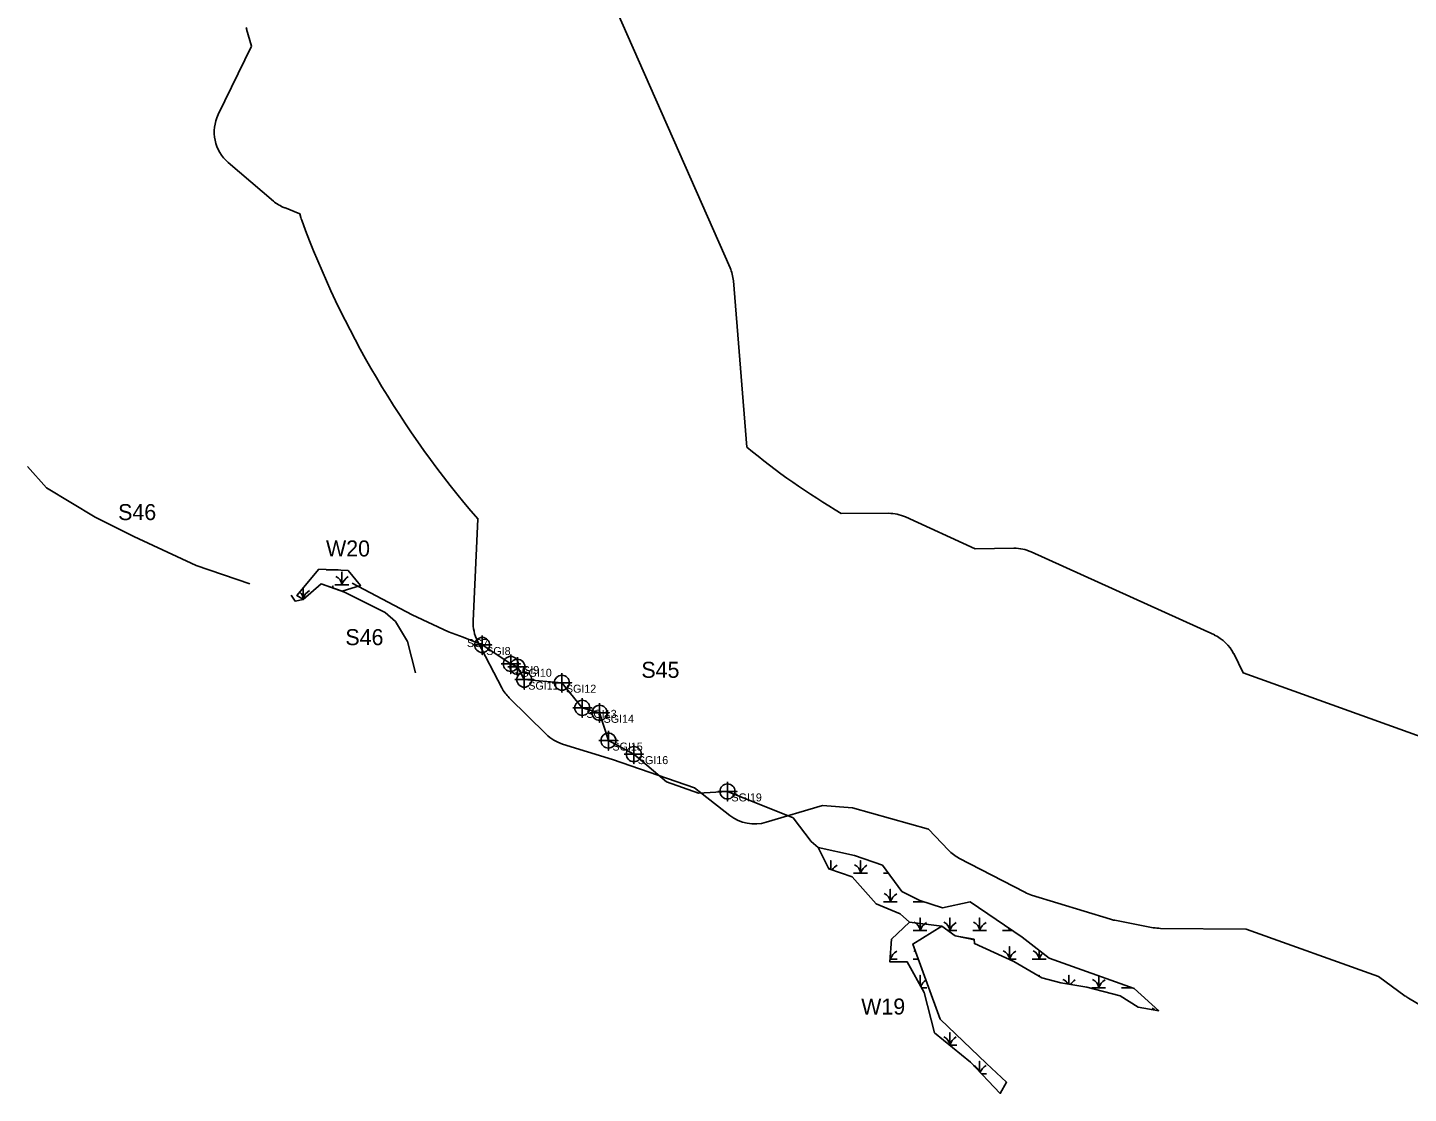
# Model space of a CAD drawing. Extents: x 1253697 to 1278588, y 912189 to 981699.
# Drawn here: x 1261409 to 1263135, y 937677 to 939009 of the extents above; entities that cross this region are included whole.
import ezdxf

# ---------------------------------------------------------------- set-up
doc = ezdxf.new("R2010")
doc.units = 0
for name, color, linetype in [('Default', 7, 'Continuous'), ('Exist Environmental Wetland Boundary', 7, 'Continuous'), ('Exist Hydro Jurisdictional Stream or Body of Water Mitigable', 7, 'Continuous'), ('Exist Hydro Jurisdictional Stream or Body of Water Mitigable Cogo Comment', 7, 'Continuous'), ('Exist Hydro Jurisdictional Stream or Body of Water Mitigable Cogo Number', 7, 'Continuous'), ('Exist Hydro Jurisdictional Stream or Body of Water Mitigable Cogo Point CELL', 7, 'Continuous'), ('Exist Hydro Swamp or Marsh', 7, 'Continuous')]:
    doc.layers.add(name, color=color, linetype=linetype)

msp = doc.modelspace()

# ---------------------------------------------------------------- linework, layer by layer
at = {"layer": 'Default'}
for p, q in [((1262287, 938708.6), (1262120.5, 939086.2)), ((1262287, 938708.6), (1262120.5, 939086.2)), ((1262287, 938708.6), (1262120.5, 939086.2)), ((1262287, 938708.6), (1262120.5, 939086.2)), ((1261659.9, 938840), (1261716.3, 938792)), ((1261659.9, 938840), (1261716.3, 938792)), ((1261659.9, 938840), (1261716.3, 938792)), ((1261659.9, 938840), (1261716.3, 938792)), ((1262307.8, 938484.5), (1262291.1, 938692.4)), ((1262307.8, 938484.5), (1262291.1, 938692.4)), ((1262307.8, 938484.5), (1262291.1, 938692.4)), ((1262307.8, 938484.5), (1262291.1, 938692.4)), ((1262485.1, 938401.9), (1262425.9, 938401.8)), ((1262485.1, 938401.9), (1262425.9, 938401.8)), ((1262485.1, 938401.9), (1262425.9, 938401.8)), ((1262485.1, 938401.9), (1262425.9, 938401.8)), ((1261971.9, 938394.7), (1261965.8, 938267.6)), ((1261971.9, 938394.7), (1261965.8, 938267.6)), ((1261971.9, 938394.7), (1261965.8, 938267.6)), ((1261971.9, 938394.7), (1261965.8, 938267.6)), ((1262892.2, 938249.9), (1262663.1, 938353.8)), ((1262892.2, 938249.9), (1262663.1, 938353.8)), ((1262892.2, 938249.9), (1262663.1, 938353.8)), ((1262892.2, 938249.9), (1262663.1, 938353.8)), ((1261971.4, 938242.1), (1262001.7, 938184)), ((1261971.4, 938242.1), (1262001.7, 938184)), ((1261971.4, 938242.1), (1262001.7, 938184)), ((1261971.4, 938242.1), (1262001.7, 938184)), ((1262010.9, 938171.5), (1262057, 938125.9)), ((1262010.9, 938171.5), (1262057, 938125.9)), ((1262010.9, 938171.5), (1262057, 938125.9)), ((1262010.9, 938171.5), (1262057, 938125.9)), ((1262572.9, 937971.3), (1262655.5, 937928.5)), ((1262572.9, 937971.3), (1262655.5, 937928.5)), ((1262572.9, 937971.3), (1262655.5, 937928.5)), ((1262572.9, 937971.3), (1262655.5, 937928.5)), ((1262663.8, 937925.1), (1262762.3, 937894.9)), ((1262663.8, 937925.1), (1262762.3, 937894.9)), ((1262663.8, 937925.1), (1262762.3, 937894.9)), ((1262663.8, 937925.1), (1262762.3, 937894.9)), ((1262767.6, 937893.5), (1262815.9, 937884.3)), ((1262767.6, 937893.5), (1262815.9, 937884.3)), ((1262767.6, 937893.5), (1262815.9, 937884.3)), ((1262767.6, 937893.5), (1262815.9, 937884.3)), ((1263134.6, 937796.3), (1263224.7, 937742.8)), ((1263134.6, 937796.3), (1263224.7, 937742.8)), ((1263134.6, 937796.3), (1263224.7, 937742.8)), ((1263134.6, 937796.3), (1263224.7, 937742.8))]:
    msp.add_line(p, q, dxfattribs=at)
for points in [[(1261682.8, 939006.8), (1261688.9, 938985.4), (1261647.3, 938900)], [(1261682.8, 939006.8), (1261688.9, 938985.4), (1261647.3, 938900)], [(1261682.8, 939006.8), (1261688.9, 938985.4), (1261647.3, 938900)], [(1261682.8, 939006.8), (1261688.9, 938985.4), (1261647.3, 938900)], [(1261730, 938783.7), (1261749.3, 938775.9), (1261750.5, 938771.4)], [(1261730, 938783.7), (1261749.3, 938775.9), (1261750.5, 938771.4)], [(1261730, 938783.7), (1261749.3, 938775.9), (1261750.5, 938771.4)], [(1261730, 938783.7), (1261749.3, 938775.9), (1261750.5, 938771.4)], [(1262641.7, 938358.2), (1262593.1, 938357.5), (1262506.1, 938397.4)], [(1262641.7, 938358.2), (1262593.1, 938357.5), (1262506.1, 938397.4)], [(1262641.7, 938358.2), (1262593.1, 938357.5), (1262506.1, 938397.4)], [(1262641.7, 938358.2), (1262593.1, 938357.5), (1262506.1, 938397.4)], [(1263346.7, 938104.1), (1263218.8, 938098.3), (1262928.3, 938202.5), (1262916.3, 938226.6)], [(1263346.7, 938104.1), (1263218.8, 938098.3), (1262928.3, 938202.5), (1262916.3, 938226.6)], [(1263346.7, 938104.1), (1263218.8, 938098.3), (1262928.3, 938202.5), (1262916.3, 938226.6)], [(1263346.7, 938104.1), (1263218.8, 938098.3), (1262928.3, 938202.5), (1262916.3, 938226.6)], [(1262077.5, 938113.7), (1262140, 938094.5), (1262242.5, 938059.1), (1262286.8, 938024.4)], [(1262077.5, 938113.7), (1262140, 938094.5), (1262242.5, 938059.1), (1262286.8, 938024.4)], [(1262077.5, 938113.7), (1262140, 938094.5), (1262242.5, 938059.1), (1262286.8, 938024.4)], [(1262077.5, 938113.7), (1262140, 938094.5), (1262242.5, 938059.1), (1262286.8, 938024.4)], [(1262332.1, 938015.9), (1262402.3, 938037.1), (1262440, 938033.9), (1262534.8, 938007.3), (1262559.8, 937981.2)], [(1262332.1, 938015.9), (1262402.3, 938037.1), (1262440, 938033.9), (1262534.8, 938007.3), (1262559.8, 937981.2)], [(1262332.1, 938015.9), (1262402.3, 938037.1), (1262440, 938033.9), (1262534.8, 938007.3), (1262559.8, 937981.2)], [(1262332.1, 938015.9), (1262402.3, 938037.1), (1262440, 938033.9), (1262534.8, 938007.3), (1262559.8, 937981.2)], [(1262824.8, 937883.4), (1262932, 937882.5), (1263097.2, 937823.2), (1263130.8, 937798.8)], [(1262824.8, 937883.4), (1262932, 937882.5), (1263097.2, 937823.2), (1263130.8, 937798.8)], [(1262824.8, 937883.4), (1262932, 937882.5), (1263097.2, 937823.2), (1263130.8, 937798.8)], [(1262824.8, 937883.4), (1262932, 937882.5), (1263097.2, 937823.2), (1263130.8, 937798.8)]]:
    msp.add_lwpolyline(points, dxfattribs=at)
for centre, radius, start, end in [((1261730.9, 939020.6), 50, 193.9029, 196.0582), ((1261730.9, 939020.6), 50, 193.9029, 196.0582), ((1261730.9, 939020.6), 50, 193.9029, 196.0582), ((1261730.9, 939020.6), 50, 193.9029, 196.0582), ((1261692.3, 938878.1), 50, 154.043, 229.5688), ((1261692.3, 938878.1), 50, 154.043, 229.5688), ((1261692.3, 938878.1), 50, 154.043, 229.5688), ((1261692.3, 938878.1), 50, 154.043, 229.5688), ((1261748.7, 938830), 50, 229.5688, 248.0174), ((1261748.7, 938830), 50, 229.5688, 248.0174), ((1261748.7, 938830), 50, 229.5688, 248.0174), ((1261748.7, 938830), 50, 229.5688, 248.0174), ((1261798.6, 938785.3), 50, 196.0582, 200.2271), ((1261798.6, 938785.3), 50, 196.0582, 200.2271), ((1261798.6, 938785.3), 50, 196.0582, 200.2271), ((1261798.6, 938785.3), 50, 196.0582, 200.2271), ((1262887.1, 939186.3), 1210, 200.2271, 220.8587), ((1262887.1, 939186.3), 1210, 200.2271, 220.8587), ((1262887.1, 939186.3), 1210, 200.2271, 220.8587), ((1262887.1, 939186.3), 1210, 200.2271, 220.8587), ((1262241.2, 938688.4), 50, 4.6096, 23.7913), ((1262241.2, 938688.4), 50, 4.6096, 23.7913), ((1262241.2, 938688.4), 50, 4.6096, 23.7913), ((1262241.2, 938688.4), 50, 4.6096, 23.7913), ((1262887.1, 939186.3), 910, 230.4683, 239.5487), ((1262887.1, 939186.3), 910, 230.4683, 239.5487), ((1262887.1, 939186.3), 910, 230.4683, 239.5487), ((1262887.1, 939186.3), 910, 230.4683, 239.5487), ((1262485.2, 938351.9), 50, 65.3602, 90.1023), ((1262485.2, 938351.9), 50, 65.3602, 90.1023), ((1262485.2, 938351.9), 50, 65.3602, 90.1023), ((1262485.2, 938351.9), 50, 65.3602, 90.1023), ((1262642.5, 938308.2), 50, 65.6013, 90.9113), ((1262642.5, 938308.2), 50, 65.6013, 90.9113), ((1262642.5, 938308.2), 50, 65.6013, 90.9113), ((1262642.5, 938308.2), 50, 65.6013, 90.9113), ((1262015.8, 938265.2), 50, 177.2605, 207.4964), ((1262015.8, 938265.2), 50, 177.2605, 207.4964), ((1262015.8, 938265.2), 50, 177.2605, 207.4964), ((1262015.8, 938265.2), 50, 177.2605, 207.4964), ((1262871.5, 938204.3), 50, 26.5045, 65.6013), ((1262871.5, 938204.3), 50, 26.5045, 65.6013), ((1262871.5, 938204.3), 50, 26.5045, 65.6013), ((1262871.5, 938204.3), 50, 26.5045, 65.6013), ((1262046, 938207.1), 50, 207.4964, 225.3691), ((1262046, 938207.1), 50, 207.4964, 225.3691), ((1262046, 938207.1), 50, 207.4964, 225.3691), ((1262046, 938207.1), 50, 207.4964, 225.3691), ((1262092.2, 938161.5), 50, 225.3691, 252.9122), ((1262092.2, 938161.5), 50, 225.3691, 252.9122), ((1262092.2, 938161.5), 50, 225.3691, 252.9122), ((1262092.2, 938161.5), 50, 225.3691, 252.9122), ((1262317.6, 938063.8), 50, 231.9729, 286.8021), ((1262317.6, 938063.8), 50, 231.9729, 286.8021), ((1262317.6, 938063.8), 50, 231.9729, 286.8021), ((1262317.6, 938063.8), 50, 231.9729, 286.8021), ((1262596, 938015.7), 50, 223.6682, 242.5856), ((1262596, 938015.7), 50, 223.6682, 242.5856), ((1262596, 938015.7), 50, 223.6682, 242.5856), ((1262596, 938015.7), 50, 223.6682, 242.5856), ((1262678.5, 937972.9), 50, 242.5856, 252.9404), ((1262678.5, 937972.9), 50, 242.5856, 252.9404), ((1262678.5, 937972.9), 50, 242.5856, 252.9404), ((1262678.5, 937972.9), 50, 242.5856, 252.9404), ((1262777, 937942.7), 50, 252.9404, 259.1998), ((1262777, 937942.7), 50, 252.9404, 259.1998), ((1262777, 937942.7), 50, 252.9404, 259.1998), ((1262777, 937942.7), 50, 252.9404, 259.1998), ((1262825.3, 937933.4), 50, 259.1998, 269.4694), ((1262825.3, 937933.4), 50, 259.1998, 269.4694), ((1262825.3, 937933.4), 50, 259.1998, 269.4694), ((1262825.3, 937933.4), 50, 259.1998, 269.4694), ((1263160.2, 937839.3), 50, 234.021, 239.3165), ((1263160.2, 937839.3), 50, 234.021, 239.3165), ((1263160.2, 937839.3), 50, 234.021, 239.3165), ((1263160.2, 937839.3), 50, 234.021, 239.3165)]:
    msp.add_arc(centre, radius, start, end, dxfattribs=at)
at = {"layer": 'Exist Environmental Wetland Boundary'}
for p, q in [((1262478.6, 937952.2), (1262484.9, 937952.2)), ((1262515.8, 937844.9), (1262522.2, 937844.9)), ((1262526.3, 937809.1), (1262533, 937809.1)), ((1262822, 937780.6), (1262822, 937781)), ((1262822, 937781), (1262822, 937780.6)), ((1262561.6, 937737.5), (1262570.2, 937737.5)), ((1262601.2, 937701.7), (1262607.4, 937701.7))]:
    msp.add_line(p, q, dxfattribs=at)
for points in [[(1261809.6, 938330.6), (1261825.2, 938311.8), (1261802.3, 938304.8), (1261776.1, 938313.6), (1261753.7, 938294.3), (1261745.6, 938299.1), (1261773.1, 938332.2)], [(1262397.1, 937984.4), (1262442.6, 937974.3), (1262477.4, 937962.3), (1262501.7, 937929.6), (1262524.1, 937918.1), (1262552.4, 937909), (1262587.1, 937916.6), (1262651.8, 937872.5), (1262685.6, 937846.4), (1262791.9, 937808.4), (1262822.6, 937780.5), (1262796.8, 937785), (1262774.6, 937799.1), (1262732.9, 937810.1), (1262700.3, 937815.4), (1262676.4, 937821.7), (1262641.7, 937842.2), (1262592.4, 937864.4), (1262591.9, 937869.9), (1262568.2, 937874.3), (1262551.5, 937886.3), (1262515.3, 937863.8), (1262549.5, 937769.9), (1262607.4, 937714.8), (1262632.6, 937691.3), (1262624.5, 937677.3), (1262587.4, 937716.2), (1262542.6, 937753.1), (1262529.6, 937803.2), (1262508.3, 937841.6), (1262486.7, 937841.5), (1262488.7, 937870.1), (1262511.1, 937891.3), (1262499.5, 937901.4), (1262469.7, 937913.9), (1262439.6, 937947.7), (1262410.3, 937957.7)]]:
    msp.add_lwpolyline(points, close=True, dxfattribs=at)
for points in [[(1261782, 938331.1), (1261790.6, 938331.1), (1261790.6, 938331.4)], [(1261790.6, 938331.4), (1261790.6, 938331.1), (1261797, 938331.1)], [(1261751.9, 938295.4), (1261753.4, 938295.4), (1261753.4, 938308.3)], [(1261753.4, 938308.3), (1261753.4, 938295.4), (1261754.9, 938295.4)], [(1261790.6, 938308.7), (1261790.6, 938311.1), (1261790.6, 938308.7)], [(1262412.7, 937956.9), (1262412.7, 937968), (1262412.7, 937956.9)], [(1262441.3, 937952.2), (1262449.9, 937952.2), (1262449.9, 937968), (1262449.9, 937952.2), (1262458.6, 937952.2)], [(1262478.6, 937916.4), (1262487.2, 937916.4), (1262487.2, 937932.2), (1262487.2, 937916.4), (1262495.8, 937916.4)], [(1262515.8, 937916.4), (1262524.4, 937916.4), (1262524.4, 937918)], [(1262524.4, 937918), (1262524.4, 937916.4), (1262529.2, 937916.4)], [(1262515.8, 937880.7), (1262524.4, 937880.7), (1262524.4, 937896.4), (1262524.4, 937880.7), (1262533, 937880.7)], [(1262559.4, 937880.7), (1262561.6, 937880.7), (1262561.6, 937896.4), (1262561.6, 937880.7), (1262570.2, 937880.7)], [(1262590.2, 937880.7), (1262598.8, 937880.7), (1262598.8, 937896.4), (1262598.8, 937880.7), (1262607.4, 937880.7)], [(1262627.4, 937880.7), (1262636, 937880.7), (1262636, 937883.3)], [(1262636, 937883.3), (1262636, 937880.7), (1262639.9, 937880.7)], [(1262486.9, 937844.9), (1262487.2, 937844.9), (1262487.2, 937848.6)], [(1262487.2, 937848.6), (1262487.2, 937844.9), (1262495.8, 937844.9)], [(1262635.7, 937844.9), (1262636, 937844.9), (1262636, 937860.7), (1262636, 937844.9), (1262644.6, 937844.9)], [(1262664.6, 937844.9), (1262673.2, 937844.9), (1262673.2, 937856)], [(1262673.2, 937856), (1262673.2, 937844.9), (1262681.8, 937844.9)], [(1262524.4, 937812.5), (1262524.4, 937824.9), (1262524.4, 937812.5)], [(1262673.2, 937823.6), (1262673.2, 937824.9), (1262673.2, 937823.6)], [(1262710.4, 937813.8), (1262710.4, 937824.9), (1262710.4, 937813.8)], [(1262739, 937809.1), (1262747.6, 937809.1), (1262747.6, 937824.2)], [(1262747.6, 937824.2), (1262747.6, 937809.1), (1262756.2, 937809.1)], [(1262776.2, 937809.1), (1262784.8, 937809.1), (1262784.8, 937810.9)], [(1262784.8, 937810.9), (1262784.8, 937809.1), (1262789.9, 937809.1)], [(1262561.6, 937737.5), (1262561.6, 937753.3), (1262561.6, 937737.5)], [(1262598.8, 937704.3), (1262598.8, 937717.5), (1262598.8, 937704.3)]]:
    msp.add_lwpolyline(points, dxfattribs=at)
for centre, radius, start, end in [((1261778.3, 938330.3), 12.3, 4.1403, 5.4329), ((1261808.8, 938325.1), 19.2, 160.7673, 161.6222), ((1261741.1, 938294.5), 12.3, 4.1403, 47.6144), ((1261771.6, 938289.3), 19.2, 122.1274, 161.6222), ((1262400.5, 937951.3), 12.3, 29.8437, 44.7139), ((1262431, 937946.2), 19.2, 122.1274, 148.3148), ((1262437.7, 937951.3), 12.3, 4.1403, 67.535), ((1262468.2, 937946.2), 19.2, 122.1274, 161.6222), ((1262474.9, 937915.5), 12.3, 4.1403, 67.535), ((1262505.4, 937910.4), 19.2, 122.1274, 161.6222), ((1262512.1, 937915.5), 12.3, 4.1403, 11.7821), ((1262542.6, 937910.4), 19.2, 157.2155, 161.6222), ((1262512.1, 937879.8), 12.3, 4.1403, 67.535), ((1262542.6, 937874.6), 19.2, 122.1274, 161.6222), ((1262549.3, 937879.8), 12.3, 4.1403, 67.535), ((1262579.8, 937874.6), 19.2, 122.1274, 161.6222), ((1262586.5, 937879.8), 12.3, 4.1403, 67.535), ((1262617, 937874.6), 19.2, 122.1274, 161.6222), ((1262623.7, 937879.8), 12.3, 4.1403, 18.8781), ((1262654.2, 937874.6), 19.2, 154.8982, 161.6222), ((1262505.4, 937838.8), 19.2, 122.1274, 161.6222), ((1262512.1, 937844), 12.3, 57.1048, 67.535), ((1262623.7, 937844), 12.3, 4.1403, 67.535), ((1262654.2, 937838.8), 19.2, 122.1274, 161.6222), ((1262660.9, 937844), 12.3, 4.1403, 67.535), ((1262691.4, 937838.8), 19.2, 134.9261, 161.6222), ((1262474.9, 937844), 12.3, 4.1403, 10.3776), ((1262542.6, 937803), 19.2, 124.6479, 155.1692), ((1262698.1, 937808.2), 12.3, 28.0907, 67.535), ((1262728.6, 937803), 19.2, 122.1274, 147.2362), ((1262735.3, 937808.2), 12.3, 4.1403, 67.535), ((1262765.8, 937803), 19.2, 122.1274, 161.6222), ((1262772.5, 937808.2), 12.3, 4.1403, 13.3475), ((1262803, 937803), 19.2, 156.4444, 161.6222), ((1262809.7, 937772.4), 12.3, 45.8252, 67.535), ((1262549.3, 937736.6), 12.3, 4.1718, 67.535), ((1262579.8, 937731.5), 19.2, 122.1274, 161.6066), ((1262586.5, 937700.9), 12.3, 20.1159, 67.1501), ((1262617, 937695.7), 19.2, 122.1274, 155.743)]:
    msp.add_arc(centre, radius, start, end, dxfattribs=at)
at = {"layer": 'Exist Hydro Jurisdictional Stream or Body of Water Mitigable'}
for points in [[(1261687, 938313.6), (1261619.8, 938336.5), (1261541.7, 938373.1), (1261493.7, 938396.9), (1261432.9, 938433.6), (1261409.1, 938460.2)], [(1261894, 938202.6), (1261884, 938241.6), (1261868.8, 938266.9), (1261856, 938278.1), (1261805.3, 938303.4), (1261776.1, 938313.6), (1261753.5, 938294.1), (1261743.3, 938292.2), (1261738.3, 938299.7)], [(1262592.4, 937869), (1262568.2, 937874.3), (1262551.5, 937886.3), (1262511.1, 937891.3), (1262499.5, 937901.4), (1262469.7, 937913.9), (1262439.6, 937947.7), (1262410.3, 937957.7), (1262397.1, 937984.4), (1262388.3, 937991.9), (1262365.6, 938021.7), (1262283.7, 938054.5), (1262247.4, 938052.5), (1262207.6, 938066.6), (1262166.7, 938101.1), (1262134.9, 938118), (1262123.9, 938152.7), (1262102.3, 938158.9), (1262076.8, 938190.3), (1262029.8, 938194.1), (1262021.2, 938210.2), (1262012.9, 938213.7), (1261977.2, 938237.4), (1261953.2, 938247.3), (1261935.2, 938254), (1261889.6, 938275.1), (1261814.5, 938314.6)]]:
    msp.add_lwpolyline(points, dxfattribs=at)
at = {"layer": 'Exist Hydro Jurisdictional Stream or Body of Water Mitigable Cogo Point CELL'}
for points in [[(1261977.2, 938249.4), (1261977.2, 938225.4), (1261977.2, 938237.4), (1261989.2, 938237.4), (1261965.2, 938237.4)], [(1262012.9, 938225.7), (1262012.9, 938201.7), (1262012.9, 938213.7), (1262024.9, 938213.7), (1262000.9, 938213.7)], [(1262021.2, 938222.2), (1262021.2, 938198.2), (1262021.2, 938210.2), (1262033.2, 938210.2), (1262009.2, 938210.2)], [(1262029.8, 938206.1), (1262029.8, 938182.1), (1262029.8, 938194.1), (1262041.8, 938194.1), (1262017.8, 938194.1)], [(1262076.8, 938202.3), (1262076.8, 938178.3), (1262076.8, 938190.3), (1262088.8, 938190.3), (1262064.8, 938190.3)], [(1262102.3, 938170.9), (1262102.3, 938146.9), (1262102.3, 938158.9), (1262114.3, 938158.9), (1262090.3, 938158.9)], [(1262123.9, 938164.7), (1262123.9, 938140.7), (1262123.9, 938152.7), (1262135.9, 938152.7), (1262111.9, 938152.7)], [(1262134.9, 938130), (1262134.9, 938106), (1262134.9, 938118), (1262146.9, 938118), (1262122.9, 938118)], [(1262166.7, 938113.1), (1262166.7, 938089.1), (1262166.7, 938101.1), (1262178.7, 938101.1), (1262154.7, 938101.1)], [(1262283.7, 938066.5), (1262283.7, 938042.5), (1262283.7, 938054.5), (1262295.7, 938054.5), (1262271.7, 938054.5)]]:
    msp.add_lwpolyline(points, dxfattribs=at)
for centre in [(1261977.2, 938237.4), (1262012.9, 938213.7), (1262021.2, 938210.2), (1262029.8, 938194.1), (1262076.8, 938190.3), (1262102.3, 938158.9), (1262123.9, 938152.7), (1262134.9, 938118), (1262166.7, 938101.1), (1262283.7, 938054.5)]:
    msp.add_circle(centre, 9.38, dxfattribs=at)
at = {"layer": 'Exist Hydro Swamp or Marsh'}
msp.add_line((1261801.8, 938319.8), (1261801.8, 938319.8), dxfattribs=at)
msp.add_lwpolyline([(1261793.2, 938312.6), (1261801.8, 938312.6), (1261801.8, 938328.4), (1261801.8, 938312.6), (1261810.4, 938312.6)], dxfattribs=at)
for centre, radius, start, end in [((1261789.6, 938311.8), 12.3, 4.1403, 67.535), ((1261820.1, 938306.6), 19.2, 122.1274, 161.6222)]:
    msp.add_arc(centre, radius, start, end, dxfattribs=at)

# ---------------------------------------------------------------- texts
at = {"layer": 'Exist Hydro Jurisdictional Stream or Body of Water Mitigable Cogo Comment'}
for s, p in [('SG7', (1261958.2, 938234.8)), ('SGI8', (1261982.2, 938224.9)), ('SGI9', (1262017.9, 938201.2)), ('SGI10', (1262026.2, 938197.7)), ('SGI11', (1262034.8, 938181.6)), ('SGI12', (1262081.8, 938177.8)), ('SGI13', (1262107.3, 938146.4)), ('SGI14', (1262128.9, 938140.2)), ('SGI15', (1262139.9, 938105.5)), ('SGI16', (1262171.7, 938088.6)), ('SGI19', (1262288.7, 938042))]:
    msp.add_text(s, height=10, dxfattribs=at).set_placement(p)
at = {"layer": 'Exist Hydro Jurisdictional Stream or Body of Water Mitigable Cogo Number'}
msp.add_text('S45', height=20, dxfattribs=at).set_placement((1262176.1, 938196.4))
at = {"layer": 'Exist Hydro Swamp or Marsh'}
for s, p in [('S46', (1261522.2, 938393.4)), ('W20', (1261782, 938348)), ('S46', (1261806.2, 938237.2)), ('W19', (1262450.8, 937775.8))]:
    msp.add_text(s, height=20, dxfattribs=at).set_placement(p)

doc.saveas('drawing.dxf')
